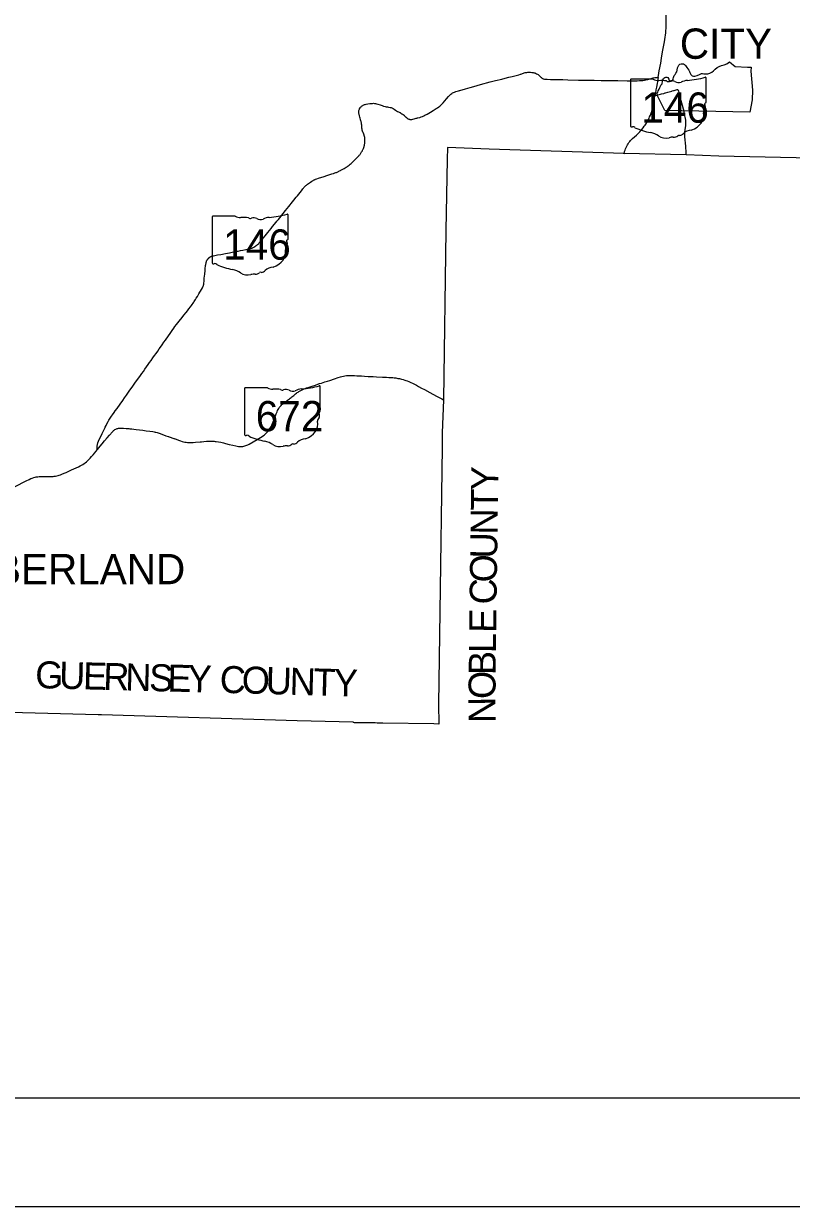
# Model space of a CAD drawing. Extents: x 1913970 to 2397567, y 78841 to 829347.
# Drawn here: x 2211369 to 2239770, y 653347 to 697090 of the extents above; entities that cross this region are included whole.
import ezdxf

# ---------------------------------------------------------------- set-up
doc = ezdxf.new("R2010")
doc.units = 0
for name, color, linetype in [('GM_X_Corporation', 7, 'Continuous'), ('GM_X_Corporation_Text', 7, 'Continuous'), ('GM_X_County', 7, 'Continuous'), ('GM_X_County_Text', 7, 'Continuous'), ('GM_X_State_Location', 7, 'Continuous'), ('GM_X_State_Route', 7, 'Continuous'), ('GM_X_State_Shield', 7, 'Continuous'), ('SH_Border', 7, 'Continuous'), ('SH_Cut_Line', 7, 'Continuous')]:
    doc.layers.add(name, color=color, linetype=linetype)

msp = doc.modelspace()

# ---------------------------------------------------------------- linework, layer by layer
at = {"layer": 'GM_X_Corporation'}
msp.add_lwpolyline([(2234811, 694526), (2234826, 694560), (2234847, 694610), (2234875, 694667), (2234902, 694735), (2234929, 694775), (2234946, 694813), (2234974, 694847), (2234989, 694866), (2234991, 694889), (2234997, 694935), (2235005, 694963), (2235014, 695009), (2235035, 695055), (2235050, 695078), (2235085, 695100), (2235126, 695112), (2235166, 695112), (2235203, 695102), (2235233, 695036), (2235246, 694998), (2235303, 694958), (2235328, 694963), (2235355, 694975), (2235393, 695019), (2235402, 695055), (2235408, 695093), (2235425, 695135), (2235435, 695173), (2235469, 695216), (2235500, 695257), (2235531, 695306), (2235545, 695368), (2235562, 695451), (2235580, 695510), (2235604, 695555), (2235646, 695593), (2235694, 695604), (2235781, 695600), (2235815, 695576), (2235850, 695538), (2235899, 695465), (2235978, 695365), (2236006, 695320), (2236020, 695278), (2236051, 695212), (2236099, 695160), (2236144, 695143), (2236200, 695143), (2236287, 695174), (2236366, 695205), (2236442, 695244), (2236477, 695247), (2236533, 695240), (2236619, 695230), (2236685, 695230), (2236720, 695247), (2236751, 695261), (2236827, 695299), (2236886, 695351), (2236952, 695410), (2237021, 695469), (2237101, 695510), (2237184, 695545), (2237281, 695573), (2237381, 695607), (2237478, 695677), (2237697, 695504), (2238146, 695487), (2238284, 695484), (2238275, 695329), (2238334, 694628), (2238314, 694270), (2238234, 693813), (2235084, 693873), (2234825, 694402), (2234812, 694441), (2234806, 694467), (2234803, 694493)], close=True, dxfattribs=at)
at = {"layer": 'GM_X_County'}
msp.add_lwpolyline([(2240515, 692110), (2237090, 692186), (2235874, 692235), (2233577, 692284), (2228587, 692451), (2227052, 692504), (2227039, 692060), (2226989, 689439), (2226900, 683181), (2226857, 681954), (2226847, 681422), (2226765, 675340), (2226717, 671919), (2226734, 671182), (2226543, 671187), (2224661, 671212), (2224605, 671215), (2224557, 671217), (2224488, 671219), (2224446, 671221), (2224374, 671224), (2224280, 671227), (2224235, 671227), (2224212, 671227), (2224176, 671228), (2224022, 671231), (2223970, 671231), (2223610, 671236), (2223585, 671239), (2223570, 671244), (2223558, 671250), (2221486, 671307), (2214244, 671522), (2214128, 671527), (2207126, 671715)], dxfattribs=at)
at = {"layer": 'GM_X_State_Route'}
for p, q in [((2234723, 694420), (2234807, 694444)), ((2216723, 681817), (2216755, 681806)), ((2213741, 680931), (2213763, 680953))]:
    msp.add_line(p, q, dxfattribs=at)
for points in [[(2234970, 695820), (2234972, 695831), (2235021, 696105), (2235074, 696412), (2235103, 696587), (2235114, 696668), (2235123, 696753), (2235129, 696828), (2235134, 696929), (2235137, 697044), (2235138, 697168), (2235139, 697401), (2235139, 697677), (2235139, 697821), (2235139, 698028), (2235139, 698130), (2235138, 698247), (2235139, 698323)], [(2234842, 695097), (2234870, 695261), (2234885, 695346), (2234936, 695634), (2234970, 695820)], [(2218050, 687641), (2218053, 687676), (2218066, 687826), (2218078, 687960), (2218090, 688064), (2218096, 688109), (2218100, 688145), (2218106, 688180), (2218110, 688209), (2218115, 688232), (2218120, 688252), (2218124, 688270), (2218129, 688285), (2218134, 688300), (2218139, 688312), (2218144, 688324), (2218149, 688334), (2218155, 688344), (2218162, 688356), (2218171, 688369), (2218177, 688377), (2218183, 688386), (2218189, 688393), (2218195, 688399), (2218204, 688410), (2218214, 688421), (2218224, 688430), (2218233, 688438), (2218244, 688447), (2218256, 688456), (2218268, 688464), (2218281, 688472), (2218293, 688478), (2218305, 688484), (2218316, 688488), (2218326, 688492), (2218338, 688495), (2218350, 688498), (2218369, 688503), (2218391, 688507), (2218546, 688535), (2218659, 688556), (2218836, 688590), (2218990, 688620), (2219138, 688649), (2219244, 688670), (2219302, 688681), (2219396, 688698), (2219483, 688713), (2219583, 688732), (2219670, 688749), (2219691, 688753), (2219712, 688758), (2219733, 688763), (2219753, 688769), (2219774, 688775), (2219794, 688782), (2219817, 688791), (2219840, 688801), (2219860, 688809), (2219879, 688819), (2219893, 688826), (2219908, 688834), (2219922, 688842), (2219935, 688850), (2219949, 688860), (2219964, 688870), (2219976, 688880), (2219989, 688891), (2220021, 688920), (2220052, 688950), (2220074, 688973), (2220096, 688998), (2220116, 689020), (2220148, 689057), (2220203, 689123), (2220243, 689170), (2220306, 689246), (2220403, 689366), (2220460, 689438), (2220525, 689520), (2220580, 689589), (2220709, 689751), (2220741, 689790), (2220762, 689814), (2220792, 689849), (2220842, 689914), (2220972, 690074), (2221057, 690179), (2221181, 690331), (2221318, 690498), (2221369, 690562), (2221456, 690674), (2221498, 690728), (2221644, 690909), (2221700, 690978), (2221719, 691001), (2221739, 691026), (2221764, 691052), (2221786, 691076), (2221810, 691099), (2221830, 691117), (2221850, 691135), (2221875, 691154), (2221904, 691177), (2221938, 691202), (2221977, 691229), (2222029, 691263), (2222077, 691291), (2222097, 691303), (2222117, 691313), (2222129, 691319), (2222142, 691325), (2222157, 691332), (2222171, 691337), (2222220, 691354), (2222279, 691373), (2222486, 691439), (2222590, 691472), (2222765, 691530), (2222835, 691553), (2222884, 691570), (2222913, 691580), (2222945, 691591), (2222970, 691601), (2222993, 691610), (2223012, 691619), (2223035, 691630), (2223059, 691642), (2223087, 691656), (2223108, 691668), (2223133, 691681), (2223180, 691709), (2223225, 691735), (2223296, 691779), (2223324, 691797), (2223348, 691813), (2223375, 691833), (2223407, 691857), (2223452, 691895), (2223481, 691921), (2223556, 691991), (2223633, 692066), (2223711, 692146), (2223745, 692181), (2223764, 692202), (2223785, 692225), (2223801, 692244), (2223816, 692263), (2223830, 692281), (2223845, 692302), (2223859, 692322), (2223872, 692344), (2223885, 692364), (2223899, 692389), (2223910, 692410), (2223922, 692433), (2223931, 692452), (2223940, 692472), (2223946, 692487), (2223951, 692502), (2223957, 692519), (2223962, 692534), (2223966, 692551), (2223970, 692569), (2223975, 692588), (2223979, 692611), (2223982, 692635), (2223985, 692657), (2223988, 692683), (2223990, 692709), (2223991, 692735), (2223992, 692762), (2223993, 692785), (2223993, 692808), (2223991, 692843), (2223990, 692866), (2223987, 692887), (2223982, 692905), (2223978, 692921), (2223970, 692949), (2223963, 692971), (2223950, 693004), (2223938, 693035), (2223930, 693056), (2223904, 693120), (2223894, 693151), (2223886, 693186), (2223881, 693219), (2223880, 693258), (2223878, 693313), (2223876, 693342), (2223871, 693374), (2223863, 693409), (2223849, 693466), (2223842, 693491), (2223839, 693504), (2223833, 693523), (2223826, 693551), (2223814, 693593), (2223804, 693630), (2223790, 693684), (2223776, 693739), (2223771, 693768), (2223768, 693791), (2223766, 693820), (2223768, 693848), (2223773, 693874), (2223780, 693900), (2223789, 693925), (2223799, 693946), (2223814, 693972), (2223831, 693996), (2223851, 694019), (2223867, 694036), (2223888, 694053), (2223911, 694069), (2223933, 694081), (2223952, 694089), (2223974, 694096), (2224006, 694103), (2224042, 694110), (2224107, 694121), (2224175, 694132), (2224227, 694139), (2224276, 694143), (2224309, 694144), (2224346, 694143), (2224385, 694138), (2224427, 694128), (2224472, 694115), (2224562, 694086), (2224627, 694064), (2224687, 694044), (2224740, 694028), (2224781, 694017), (2224825, 694008), (2224861, 694003), (2224932, 693991), (2224962, 693986), (2224991, 693978), (2225015, 693968), (2225039, 693955), (2225077, 693929), (2225127, 693892), (2225165, 693867), (2225199, 693847), (2225231, 693831), (2225266, 693814), (2225287, 693804), (2225299, 693799), (2225328, 693783), (2225365, 693761), (2225384, 693748), (2225413, 693726), (2225440, 693703), (2225452, 693692), (2225461, 693683), (2225464, 693679), (2225469, 693674), (2225484, 693658), (2225491, 693652), (2225495, 693648), (2225506, 693637), (2225525, 693620), (2225530, 693616), (2225539, 693608), (2225544, 693604), (2225556, 693594), (2225566, 693586), (2225579, 693577), (2225587, 693573), (2225598, 693567), (2225618, 693559), (2225627, 693556), (2225642, 693552), (2225661, 693548), (2225680, 693547), (2225699, 693548), (2225724, 693551), (2225762, 693559), (2225817, 693572), (2225890, 693590), (2225921, 693598), (2225934, 693601), (2226023, 693625), (2226076, 693641), (2226128, 693660), (2226173, 693680), (2226216, 693702), (2226293, 693746), (2226420, 693821), (2226524, 693884), (2226631, 693948), (2226683, 693982), (2226726, 694012), (2226764, 694042), (2226800, 694075), (2226837, 694112), (2226883, 694163), (2227010, 694305), (2227088, 694390), (2227129, 694432), (2227176, 694478), (2227209, 694506), (2227239, 694526), (2227272, 694544), (2227309, 694558), (2227359, 694575), (2227457, 694602), (2227495, 694613), (2227510, 694618), (2227719, 694676), (2227889, 694724), (2228025, 694763), (2228267, 694834), (2228625, 694933), (2228819, 694983), (2229061, 695042), (2229188, 695074), (2229315, 695107), (2229443, 695139), (2229592, 695176), (2229684, 695202), (2229755, 695224), (2229763, 695227), (2229802, 695240), (2229880, 695266), (2229926, 695279), (2229963, 695286), (2229983, 695288), (2230019, 695291), (2230065, 695291), (2230121, 695290), (2230175, 695287), (2230217, 695282), (2230249, 695275), (2230275, 695268), (2230306, 695257), (2230345, 695239), (2230374, 695223), (2230402, 695205), (2230429, 695185), (2230456, 695160), (2230501, 695113), (2230523, 695093), (2230543, 695078), (2230565, 695065), (2230589, 695054), (2230604, 695048), (2230632, 695041), (2230667, 695036), (2230699, 695034), (2230739, 695033), (2230860, 695030), (2231011, 695028), (2231316, 695023), (2231506, 695018), (2231893, 695006), (2232044, 695003), (2232251, 695000), (2232477, 694996), (2232733, 694992), (2232956, 694991), (2233350, 694983), (2233691, 694979), (2233914, 694976), (2233950, 694976), (2234068, 694978), (2234147, 694982), (2234205, 694986), (2234270, 694993), (2234332, 695002), (2234390, 695013), (2234460, 695028)], [(2234460, 695028), (2234663, 695081), (2234715, 695093), (2234757, 695100), (2234797, 695102), (2234842, 695097)], [(2234842, 695097), (2234829, 695026), (2234800, 694873), (2234776, 694738)], [(2234776, 694738), (2234760, 694644), (2234738, 694518), (2234723, 694420)], [(2234807, 694444), (2234967, 694489), (2235049, 694512), (2235096, 694526), (2235118, 694533), (2235203, 694558), (2235250, 694571), (2235297, 694584), (2235345, 694597), (2235361, 694601), (2235414, 694617), (2235439, 694624), (2235503, 694641), (2235548, 694654)], [(2235548, 694654), (2235568, 694660), (2235589, 694590), (2235618, 694492), (2235660, 694335), (2235706, 694165), (2235786, 693855)], [(2233578, 692281), (2233587, 692318), (2233593, 692343), (2233601, 692368), (2233608, 692390), (2233616, 692414), (2233635, 692463), (2233656, 692511), (2233679, 692558), (2233707, 692606), (2233734, 692651), (2233763, 692694), (2233793, 692733), (2233822, 692768), (2233858, 692806), (2233898, 692845), (2234039, 692972), (2234113, 693042), (2234165, 693092), (2234203, 693133), (2234239, 693176), (2234286, 693235), (2234329, 693293), (2234363, 693342), (2234406, 693408), (2234438, 693462), (2234465, 693511), (2234508, 693599), (2234528, 693641), (2234555, 693708), (2234580, 693776), (2234604, 693847), (2234622, 693911), (2234640, 693981), (2234656, 694054), (2234675, 694154), (2234679, 694174), (2234702, 694300), (2234711, 694355), (2234723, 694420)], [(2235786, 693855), (2235810, 693727), (2235832, 693627), (2235836, 693608), (2235840, 693586), (2235853, 693518), (2235857, 693492), (2235859, 693459), (2235859, 693422), (2235857, 693380), (2235850, 693321), (2235838, 693233), (2235831, 693178), (2235827, 693145), (2235822, 693093), (2235817, 693025), (2235816, 693006), (2235817, 692944), (2235819, 692901), (2235822, 692872), (2235825, 692843), (2235827, 692823), (2235828, 692810), (2235830, 692788), (2235833, 692752), (2235837, 692706), (2235843, 692644), (2235848, 692586), (2235852, 692540), (2235857, 692491), (2235865, 692386), (2235871, 692291), (2235875, 692233)], [(2214387, 682168), (2214418, 682230), (2214450, 682291), (2214497, 682378), (2214525, 682426), (2214544, 682456), (2214573, 682499), (2214621, 682570), (2214660, 682626), (2214719, 682708), (2214759, 682764), (2214828, 682860), (2214938, 683016), (2215036, 683155), (2215105, 683251), (2215173, 683351), (2215303, 683537), (2215381, 683646), (2215433, 683718), (2215488, 683796), (2215549, 683881), (2215664, 684041), (2215739, 684145), (2215797, 684228), (2215856, 684311), (2215918, 684399), (2215979, 684485), (2216028, 684555), (2216082, 684633), (2216147, 684728), (2216210, 684816), (2216267, 684896), (2216328, 684981), (2216384, 685058), (2216431, 685125), (2216490, 685212), (2216558, 685309), (2216615, 685389), (2216809, 685666), (2216865, 685746), (2216921, 685824), (2216967, 685887), (2217028, 685965), (2217126, 686091), (2217232, 686226), (2217297, 686308), (2217375, 686405), (2217427, 686468), (2217459, 686510), (2217485, 686543), (2217537, 686615), (2217576, 686668), (2217598, 686700), (2217639, 686755), (2217659, 686784), (2217680, 686815), (2217701, 686848), (2217724, 686884), (2217740, 686909), (2217755, 686934), (2217796, 687002), (2217852, 687098), (2217947, 687259), (2217981, 687322), (2217995, 687350), (2218000, 687360), (2218006, 687374), (2218012, 687387), (2218017, 687400), (2218020, 687411), (2218024, 687424), (2218027, 687436), (2218029, 687447), (2218032, 687460), (2218033, 687471), (2218037, 687496), (2218044, 687565), (2218050, 687641)], [(2221569, 683495), (2221594, 683510), (2221620, 683525), (2221646, 683539), (2221694, 683562), (2221724, 683575), (2221782, 683599), (2221837, 683619), (2221931, 683651), (2222006, 683675), (2222081, 683698), (2222162, 683724), (2222280, 683763), (2222295, 683768), (2222314, 683775), (2222385, 683798), (2222507, 683837), (2222607, 683868), (2222696, 683897), (2222864, 683954), (2223004, 684000), (2223089, 684026), (2223139, 684040), (2223204, 684055), (2223255, 684065), (2223308, 684072), (2223347, 684076), (2223386, 684078), (2223429, 684079), (2223508, 684077), (2223603, 684072), (2223698, 684066), (2223757, 684063), (2223872, 684059), (2223983, 684052), (2224114, 684044), (2224239, 684037), (2224298, 684034), (2224426, 684029), (2224642, 684018), (2224724, 684014), (2224792, 684011), (2224881, 684007), (2224976, 684002), (2225021, 683998), (2225074, 683993), (2225132, 683985), (2225214, 683972), (2225272, 683961), (2225345, 683944), (2225412, 683927), (2225472, 683909), (2225512, 683896), (2225558, 683878), (2225622, 683852), (2225688, 683822), (2225756, 683789), (2225899, 683715), (2225977, 683674), (2226092, 683612), (2226199, 683554), (2226393, 683450), (2226648, 683314), (2226844, 683208), (2226901, 683178)], [(2216755, 681806), (2216923, 681747), (2216942, 681741), (2216967, 681733), (2216976, 681730), (2217010, 681717), (2217093, 681687), (2217176, 681659), (2217236, 681641), (2217283, 681628), (2217337, 681616), (2217385, 681608), (2217430, 681603), (2217482, 681599), (2217534, 681598), (2217606, 681601), (2217645, 681603), (2217721, 681609), (2217900, 681624), (2217943, 681628), (2218031, 681637), (2218129, 681645), (2218208, 681648), (2218270, 681650), (2218326, 681650), (2218362, 681648), (2218412, 681645), (2218454, 681641), (2218493, 681635), (2218581, 681621), (2218662, 681605), (2218761, 681584), (2218835, 681566), (2218974, 681530), (2219105, 681498), (2219213, 681473), (2219274, 681461), (2219316, 681454), (2219353, 681450), (2219358, 681449), (2219397, 681448), (2219439, 681451), (2219474, 681455), (2219513, 681463), (2219551, 681472), (2219594, 681486), (2219624, 681498), (2219663, 681515), (2219712, 681541), (2219859, 681627), (2220004, 681710), (2220137, 681789), (2220193, 681824), (2220238, 681855), (2220280, 681887), (2220317, 681918), (2220353, 681952), (2220388, 681990), (2220421, 682031), (2220448, 682068), (2220477, 682111), (2220508, 682161), (2220532, 682204), (2220548, 682236), (2220576, 682299), (2220603, 682366), (2220661, 682515), (2220714, 682653), (2220747, 682739), (2220764, 682782), (2220784, 682823), (2220806, 682861), (2220826, 682891), (2220846, 682917), (2220869, 682945), (2220897, 682973), (2220926, 683000), (2220964, 683032), (2221010, 683068), (2221030, 683083), (2221063, 683109), (2221128, 683159), (2221167, 683189), (2221201, 683215), (2221229, 683237), (2221260, 683261), (2221294, 683287), (2221328, 683313), (2221364, 683342), (2221397, 683368), (2221429, 683394), (2221462, 683419), (2221493, 683443), (2221522, 683464), (2221550, 683483), (2221569, 683495)], [(2214097, 681334), (2214092, 681356), (2214090, 681368), (2214088, 681385), (2214088, 681399), (2214089, 681425), (2214091, 681460), (2214094, 681486), (2214097, 681509), (2214101, 681531), (2214105, 681554), (2214110, 681572), (2214114, 681588), (2214118, 681602), (2214123, 681616), (2214133, 681644), (2214150, 681682), (2214208, 681800), (2214270, 681927), (2214298, 681986), (2214379, 682151), (2214387, 682168)], [(2214097, 681334), (2214201, 681464), (2214274, 681552), (2214360, 681655), (2214458, 681770), (2214540, 681868), (2214653, 681999), (2214675, 682023), (2214692, 682039), (2214713, 682057), (2214743, 682076), (2214775, 682094), (2214802, 682106), (2214827, 682114), (2214853, 682121), (2214882, 682127), (2214919, 682130), (2214965, 682130), (2215060, 682126), (2215161, 682120), (2215259, 682112), (2215301, 682109), (2215317, 682107), (2215376, 682102), (2215448, 682094), (2215526, 682084), (2215649, 682067), (2215779, 682050), (2215896, 682036), (2216040, 682018), (2216147, 682001), (2216202, 681991), (2216234, 681984), (2216263, 681977), (2216310, 681963), (2216385, 681939), (2216482, 681905), (2216629, 681851), (2216710, 681822), (2216723, 681817)], [(2213763, 680953), (2213785, 680974), (2213826, 681017), (2213879, 681075), (2213937, 681141), (2214004, 681218), (2214045, 681268), (2214097, 681334)], [(2211054, 679974), (2211461, 680179), (2211573, 680234), (2211636, 680263), (2211688, 680283), (2211741, 680301), (2211789, 680314), (2211838, 680324), (2211890, 680332), (2211942, 680337), (2212005, 680340), (2212100, 680341), (2212267, 680341), (2212385, 680342), (2212457, 680345), (2212502, 680349), (2212551, 680356), (2212599, 680365), (2212646, 680377), (2212687, 680389), (2212730, 680404), (2212781, 680425), (2212865, 680462), (2212937, 680494), (2213045, 680541), (2213138, 680583), (2213315, 680661), (2213395, 680699), (2213462, 680734), (2213513, 680762), (2213558, 680789), (2213604, 680820), (2213643, 680849), (2213692, 680888), (2213741, 680931)]]:
    msp.add_lwpolyline(points, dxfattribs=at)
at = {"layer": 'GM_X_State_Shield'}
for p, q in [((2233816, 695007), (2233816, 693306)), ((2234664, 695036), (2233843, 695036)), ((2236618, 694188), (2236618, 695078)), ((2236617, 694189), (2236618, 694188)), ((2218348, 689943), (2218348, 688241)), ((2219196, 689972), (2218375, 689972)), ((2221150, 689124), (2221150, 690014)), ((2221149, 689124), (2221150, 689124)), ((2219541, 683594), (2219541, 681893)), ((2220389, 683623), (2219568, 683623)), ((2222342, 682776), (2222342, 683666)), ((2222342, 682776), (2222342, 682776))]:
    msp.add_line(p, q, dxfattribs=at)
for centre, major_axis, start_param, end_param in [((2235620, 697356), (2971, 0), 4.814394, 5.042369), ((2236587, 695082), (31.2, 0), 6.141152, 7.989035), ((2233848, 695011), (32.5, 0), 1.712693, 3.28349), ((2234859, 695234), (315, 0), 4.042523, 4.731795), ((2234964, 694081), (1130, 0), 1.404758, 1.657858), ((2235220, 695019), (90.8, 0), 3.836095, 5.185415), ((2235354, 694823), (189, 0), 0.950623, 2.079405), ((2235597, 695092), (227, 0), 4.081561, 5.145723), ((2235999, 694517), (598, 0), 1.699011, 2.107814), ((2235786, 693703), (743, 0), 5.101752, 6.440018), ((2236729, 693816), (211, 0), 2.387724, 3.262537), ((2236610, 694123), (48.3, 0), 1.883978, 3.671073), ((2236303, 694011), (290, 0), 5.934695, 6.695948), ((2236584, 694185), (33.4, 0), 5.05454, 6.418171), ((2233848, 693302), (32.7, 0), 3.00124, 4.508301), ((2233853, 693476), (250, 0), 4.665946, 4.897461), ((2233904, 693208), (90.1, 0), 0.519207, 1.627899), ((2235042, 694736), (2146, 0), 4.195997, 4.488961), ((2234402, 692542), (671, 0), 0.823519, 1.323587), ((2235128, 693199), (426, 0), 4.026481, 4.996735), ((2235406, 693072), (227, 0), 4.691044, 5.507374), ((2235611, 692907), (63.9, 0), 1.147584, 2.315152), ((2235584, 693141), (240, 0), 4.937069, 5.64225), ((2236099, 692828), (407, 0), 1.647645, 2.488434), ((2235375, 692611), (350, 0), 1.495662, 1.94098), ((2218380, 689946), (32.5, 0), 1.712693, 3.28349), ((2219391, 690169), (315, 0), 4.042523, 4.731795), ((2219496, 689017), (1130, 0), 1.404758, 1.657858), ((2219752, 689955), (90.8, 0), 3.836095, 5.185415), ((2219886, 689758), (189, 0), 0.950623, 2.079405), ((2220129, 690028), (227, 0), 4.081561, 5.145723), ((2220530, 689452), (598, 0), 1.699011, 2.107814), ((2220152, 692291), (2971, 0), 4.814394, 5.042369), ((2221118, 690018), (31.2, 0), 6.141152, 7.989035), ((2221142, 689059), (48.3, 0), 1.883978, 3.671073), ((2220835, 688946), (290, 0), 5.934695, 6.695948), ((2221116, 689121), (33.4, 0), 5.05454, 6.418171), ((2220318, 688638), (743, 0), 5.101752, 6.440018), ((2221261, 688752), (211, 0), 2.387724, 3.262537), ((2218380, 688238), (32.7, 0), 3.00124, 4.508301), ((2218385, 688412), (250, 0), 4.665946, 4.897461), ((2218436, 688143), (90.1, 0), 0.519207, 1.627899), ((2219574, 689672), (2146, 0), 4.195997, 4.488961), ((2218934, 687477), (671, 0), 0.823519, 1.323587), ((2219660, 688135), (426, 0), 4.026481, 4.996735), ((2219906, 687547), (350, 0), 1.495662, 1.94098), ((2219938, 688007), (227, 0), 4.691044, 5.507374), ((2220143, 687843), (63.9, 0), 1.147584, 2.315152), ((2220116, 688077), (240, 0), 4.937069, 5.64225), ((2220631, 687764), (407, 0), 1.647645, 2.488434), ((2219573, 683598), (32.5, 0), 1.712693, 3.28349), ((2220584, 683821), (315, 0), 4.042523, 4.731795), ((2220689, 682668), (1130, 0), 1.404758, 1.657858), ((2220945, 683607), (90.8, 0), 3.836095, 5.185415), ((2221078, 683410), (189, 0), 0.950623, 2.079405), ((2221322, 683680), (227, 0), 4.081561, 5.145723), ((2221723, 683104), (598, 0), 1.699011, 2.107814), ((2221344, 685943), (2971, 0), 4.814394, 5.042369), ((2222311, 683669), (31.2, 0), 6.141152, 7.989035), ((2222454, 682403), (211, 0), 2.387724, 3.262537), ((2222335, 682710), (48.3, 0), 1.883978, 3.671073), ((2222028, 682598), (290, 0), 5.934695, 6.695948), ((2222309, 682772), (33.4, 0), 5.05454, 6.418171), ((2221511, 682290), (743, 0), 5.101752, 6.440018), ((2219573, 681889), (32.7, 0), 3.00124, 4.508301), ((2219578, 682063), (250, 0), 4.665946, 4.897461), ((2219629, 681795), (90.1, 0), 0.519207, 1.627899), ((2220767, 683323), (2146, 0), 4.195997, 4.488961), ((2220127, 681129), (671, 0), 0.823519, 1.323587), ((2221130, 681659), (227, 0), 4.691044, 5.507374), ((2221336, 681494), (63.9, 0), 1.147584, 2.315152), ((2221308, 681728), (240, 0), 4.937069, 5.64225), ((2221824, 681415), (407, 0), 1.647645, 2.488434), ((2220853, 681786), (426, 0), 4.026481, 4.996735), ((2221099, 681198), (350, 0), 1.495662, 1.94098)]:
    msp.add_ellipse(centre, major_axis=major_axis, ratio=0.8, start_param=start_param, end_param=end_param, dxfattribs=at)
at = {"layer": 'SH_Border'}
msp.add_lwpolyline([(2137567, 825347), (2393567, 825347), (2393567, 657347), (2137567, 657347)], close=True, dxfattribs=at)
at = {"layer": 'SH_Cut_Line'}
msp.add_lwpolyline([(2125567, 653347), (2397567, 653347), (2397567, 829347), (2125567, 829347)], close=True, dxfattribs=at)

# ---------------------------------------------------------------- texts
at = {"layer": 'GM_X_Corporation_Text'}
for s, p in [('CITY', (2235645, 695791)), ('CUMBERLAND', (2206862, 676357))]:
    msp.add_text(s, height=1120, rotation=0, dxfattribs=at).set_placement(p)
at = {"layer": 'GM_X_County_Text'}
for s, rotation, p in [('Y', 89.2289, (2228921, 679820)), ('T', 89.2286, (2228911, 679072)), ('N', 89.2287, (2228899, 678188)), ('U', 89.2287, (2228887, 677304)), ('O', 89.2289, (2228875, 676419)), ('C', 89.2288, (2228864, 675605)), ('E', 89.2311, (2228850, 674554)), ('L', 89.2485, (2228840, 673806)), ('B', 89.3168, (2228831, 672993)), ('G', 358.5324, (2211788, 672515)), ('U', 358.5328, (2212672, 672493)), ('E', 358.5322, (2213556, 672470)), ('R', 358.5324, (2214304, 672451)), ('N', 358.5327, (2215118, 672430)), ('S', 358.5323, (2216002, 672408)), ('E', 358.5322, (2216679, 672390)), ('Y', 358.5329, (2217427, 672371)), ('C', 358.5322, (2218614, 672341)), ('O', 358.5253, (2219428, 672320)), ('U', 358.2572, (2220311, 672297)), ('N', 358.3498, (2221197, 672270)), ('T', 358.4392, (2222082, 672245)), ('Y', 358.4432, (2222830, 672224)), ('O', 89.5387, (2228823, 672109)), ('N', 90.5179, (2228831, 671229))]:
    msp.add_text(s, height=1000, rotation=rotation, dxfattribs=at).set_placement(p)
at = {"layer": 'GM_X_State_Location'}
for s, p in [('146', (2234711, 694326)), ('146', (2219377, 688672)), ('672', (2220332, 682565)), ('340', (2212846, 672564))]:
    msp.add_text(s, height=1, rotation=0, dxfattribs=at).set_placement(p)
for s, p in [('s', (2235064, 694399)), ('r', (2235064, 694399)), ('s', (2219730, 688745)), ('r', (2219730, 688745)), ('s', (2220685, 682638)), ('r', (2220685, 682638)), ('s', (2213199, 672637)), ('r', (2213199, 672637))]:
    msp.add_text(s, height=1, dxfattribs=at).set_placement(p)
at = {"layer": 'GM_X_State_Shield'}
for s, p in [('146', (2234219, 693426)), ('146', (2218751, 688361)), ('672', (2219957, 682013))]:
    msp.add_text(s, height=1120.7, dxfattribs=at).set_placement(p)

doc.saveas('drawing.dxf')
